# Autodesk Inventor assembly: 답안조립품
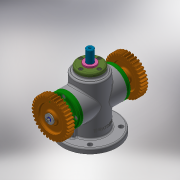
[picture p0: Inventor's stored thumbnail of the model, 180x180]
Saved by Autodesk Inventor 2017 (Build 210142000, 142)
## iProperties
Part Number: 답안조립품
Material: 일반
Document SubType Name: Assembly
Designer: 00-00
Mass: 1861.33 g
Surface Area: 1735.34 cm^2
Volume: 520.939 cm^3
Density: 3.57302 g/cm^3
Author: 00-00
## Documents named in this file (17)
- C:\Users\00-00\Desktop\600606V1016\답안조립품.iam
- C:\Users\00-00\Desktop\600606V1016\본체.ipt
- C:\Users\00-00\Desktop\600606V1016\편심축.ipt
- C:\Users\00-00\Desktop\600606V1016\Ű 4x4x12.ipt
- C:\Users\00-00\Desktop\600606V1016\베어링 6203.ipt
- C:\Users\00-00\Desktop\600606V1016\커버 A.ipt
- C:\Users\00-00\Desktop\600606V1016\오일 실 17 30 8.ipt
- C:\Users\00-00\Desktop\600606V1016\스퍼기어.ipt
- C:\Users\00-00\Desktop\600606V1016\평와셔.ipt
- C:\Users\00-00\Desktop\600606V1016\스프링와셔.ipt
- C:\Users\00-00\Desktop\600606V1016\볼트 M4.ipt
- C:\Users\00-00\Desktop\600606V1016\슬라이더.ipt
- C:\Users\00-00\Desktop\600606V1016\가변스프링.ipt
- C:\Users\00-00\Desktop\600606V1016\스프링조립용 와셔.ipt
- C:\Users\00-00\Desktop\600606V1016\멈춤링.ipt
- C:\Users\00-00\Desktop\600606V1016\부시.ipt
- C:\Users\00-00\Desktop\600606V1016\커버 B.ipt
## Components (3 placed, 2 different names)
1. Ű 4x4x12:1 — 각도:1, 각도:2
2. Ű 4x4x12:2 — 각도:3, 각도:4
3. 가변스프링:1
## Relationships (4: Angle 4)
- 각도:1 [Angle]: Ű 4x4x12:1
- 각도:2 [Angle]: Ű 4x4x12:1
- 각도:3 [Angle]: Ű 4x4x12:2
- 각도:4 [Angle]: Ű 4x4x12:2
